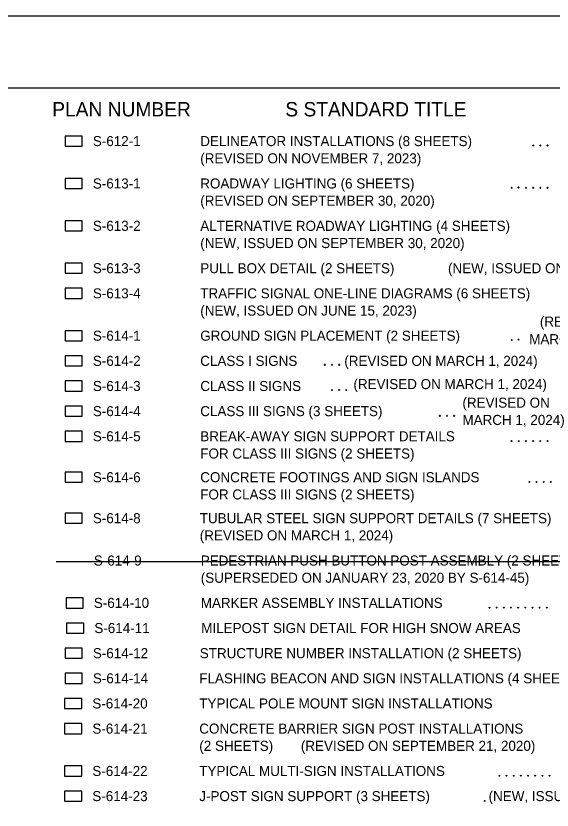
# Model space of a CAD drawing. Extents: x 0 to 1.42, y 0 to 0.92.
# Drawn here: x 0.9418 to 1.2532, y 0.4557 to 0.9167 of the extents above; entities that cross this region are included whole.
import ezdxf

# ---------------------------------------------------------------- set-up
doc = ezdxf.new("R2010")
doc.units = 0
for name, color, linetype in [('DRAFT_Text-Notes', 7, 'Continuous'), ('DRAFT_Text-Titles', 7, 'Continuous'), ('SHEET_Lines', 7, 'Continuous'), ('SHEET_Plot Boundary', 7, 'Continuous')]:
    doc.layers.add(name, color=color, linetype=linetype)

msp = doc.modelspace()

# ---------------------------------------------------------------- linework, layer by layer
at = {"layer": 'DRAFT_Text-Notes'}
for centre in [(1.2422, 0.84146), (1.24637, 0.84146), (1.25053, 0.84146), (1.2297, 0.81687), (1.23366, 0.81707), (1.23803, 0.81687), (1.2422, 0.81687), (1.24637, 0.81687), (1.25053, 0.81687), (1.2297, 0.7285), (1.23366, 0.72871), (1.12116, 0.71411), (1.12533, 0.71411), (1.12949, 0.71411), (1.12533, 0.69952), (1.12949, 0.69952), (1.13366, 0.69952), (1.18795, 0.68451), (1.19212, 0.68451), (1.19629, 0.68451), (1.22962, 0.66992), (1.23379, 0.66992), (1.23795, 0.66992), (1.24212, 0.66992), (1.24629, 0.66992), (1.25045, 0.66992), (1.23995, 0.64616), (1.24412, 0.64616), (1.24829, 0.64616), (1.25245, 0.64616), (1.21677, 0.57321), (1.22094, 0.57321), (1.2251, 0.57321), (1.22927, 0.57321), (1.23344, 0.57321), (1.2376, 0.57321), (1.24177, 0.57321), (1.24594, 0.57321), (1.2501, 0.57321), (1.22253, 0.47566), (1.2267, 0.47566), (1.23086, 0.47566), (1.23503, 0.47566), (1.2392, 0.47566), (1.24336, 0.47566), (1.24753, 0.47566), (1.2517, 0.47566), (1.21405, 0.461)]:
    msp.add_circle(centre, 0.000208, dxfattribs=at)
for centre, start, end in [((1.2422, 0.84146), 0, 180), ((1.2422, 0.84146), 180, 0), ((1.24637, 0.84146), 0, 180), ((1.24637, 0.84146), 180, 0), ((1.25053, 0.84146), 0, 180), ((1.25053, 0.84146), 180, 0), ((1.2297, 0.81687), 0, 180), ((1.2297, 0.81687), 180, 0), ((1.23366, 0.81707), 0, 180), ((1.23366, 0.81707), 180, 0), ((1.23803, 0.81687), 0, 180), ((1.23803, 0.81687), 180, 0), ((1.2422, 0.81687), 0, 180), ((1.2422, 0.81687), 180, 0), ((1.24637, 0.81687), 0, 180), ((1.24637, 0.81687), 180, 0), ((1.25053, 0.81687), 0, 180), ((1.25053, 0.81687), 180, 0), ((1.2297, 0.7285), 0, 180), ((1.2297, 0.7285), 180, 0), ((1.23366, 0.72871), 0, 180), ((1.23366, 0.72871), 180, 0), ((1.12116, 0.71411), 0, 180), ((1.12116, 0.71411), 180, 0), ((1.12533, 0.71411), 0, 180), ((1.12533, 0.71411), 180, 0), ((1.12949, 0.71411), 0, 180), ((1.12949, 0.71411), 180, 0), ((1.12533, 0.69952), 0, 180), ((1.12533, 0.69952), 180, 0), ((1.12949, 0.69952), 0, 180), ((1.12949, 0.69952), 180, 0), ((1.13366, 0.69952), 0, 180), ((1.13366, 0.69952), 180, 0), ((1.18795, 0.68451), 0, 180), ((1.18795, 0.68451), 180, 0), ((1.19212, 0.68451), 0, 180), ((1.19212, 0.68451), 180, 0), ((1.19629, 0.68451), 0, 180), ((1.19629, 0.68451), 180, 0), ((1.22962, 0.66992), 0, 180), ((1.22962, 0.66992), 180, 0), ((1.23379, 0.66992), 0, 180), ((1.23379, 0.66992), 180, 0), ((1.23795, 0.66992), 0, 180), ((1.23795, 0.66992), 180, 0), ((1.24212, 0.66992), 0, 180), ((1.24212, 0.66992), 180, 0), ((1.24629, 0.66992), 0, 180), ((1.24629, 0.66992), 180, 0), ((1.25045, 0.66992), 0, 180), ((1.25045, 0.66992), 180, 0), ((1.23995, 0.64616), 0, 180), ((1.23995, 0.64616), 180, 0), ((1.24412, 0.64616), 0, 180), ((1.24412, 0.64616), 180, 0), ((1.24829, 0.64616), 0, 180), ((1.24829, 0.64616), 180, 0), ((1.25245, 0.64616), 0, 180), ((1.25245, 0.64616), 180, 0), ((1.21677, 0.57321), 0, 180), ((1.21677, 0.57321), 180, 0), ((1.22094, 0.57321), 0, 180), ((1.22094, 0.57321), 180, 0), ((1.2251, 0.57321), 0, 180), ((1.2251, 0.57321), 180, 0), ((1.22927, 0.57321), 0, 180), ((1.22927, 0.57321), 180, 0), ((1.23344, 0.57321), 0, 180), ((1.23344, 0.57321), 180, 0), ((1.2376, 0.57321), 0, 180), ((1.2376, 0.57321), 180, 0), ((1.24177, 0.57321), 0, 180), ((1.24177, 0.57321), 180, 0), ((1.24594, 0.57321), 0, 180), ((1.24594, 0.57321), 180, 0), ((1.2501, 0.57321), 0, 180), ((1.2501, 0.57321), 180, 0), ((1.22253, 0.47566), 0, 180), ((1.22253, 0.47566), 180, 0), ((1.2267, 0.47566), 0, 180), ((1.2267, 0.47566), 180, 0), ((1.23086, 0.47566), 0, 180), ((1.23086, 0.47566), 180, 0), ((1.23503, 0.47566), 0, 180), ((1.23503, 0.47566), 180, 0), ((1.2392, 0.47566), 0, 180), ((1.2392, 0.47566), 180, 0), ((1.24336, 0.47566), 0, 180), ((1.24336, 0.47566), 180, 0), ((1.24753, 0.47566), 0, 180), ((1.24753, 0.47566), 180, 0), ((1.2517, 0.47566), 0, 180), ((1.2517, 0.47566), 180, 0), ((1.21405, 0.461), 0, 180), ((1.21405, 0.461), 180, 0)]:
    msp.add_arc(centre, 0.000208, start, end, dxfattribs=at)
at = {"layer": 'DRAFT_Text-Titles'}
msp.add_line((0.96512, 0.60007), (1.36191, 0.60007), dxfattribs=at)
at = {"layer": 'SHEET_Lines'}
msp.add_lwpolyline([(0.08333, 0.875), (1.375, 0.875), (1.375, 0.125), (0.08333, 0.125)], close=True, dxfattribs=at)
for points in [[(0.97038, 0.84102), (0.98035, 0.84102), (0.98035, 0.84691), (0.97038, 0.84691), (0.97038, 0.84102)], [(0.97038, 0.81643), (0.98035, 0.81643), (0.98035, 0.82232), (0.97038, 0.82232), (0.97038, 0.81643)], [(0.97038, 0.79184), (0.98035, 0.79184), (0.98035, 0.79773), (0.97038, 0.79773), (0.97038, 0.79184)], [(0.97038, 0.76725), (0.98035, 0.76725), (0.98035, 0.77313), (0.97038, 0.77313), (0.97038, 0.76725)], [(0.97038, 0.75266), (0.98035, 0.75266), (0.98035, 0.75854), (0.97038, 0.75854), (0.97038, 0.75266)], [(0.97038, 0.72806), (0.98035, 0.72806), (0.98035, 0.73395), (0.97038, 0.73395), (0.97038, 0.72806)], [(0.97038, 0.71347), (0.98035, 0.71347), (0.98035, 0.71936), (0.97038, 0.71936), (0.97038, 0.71347)], [(0.97038, 0.69888), (0.98035, 0.69888), (0.98035, 0.70477), (0.97038, 0.70477), (0.97038, 0.69888)], [(0.97038, 0.68429), (0.98035, 0.68429), (0.98035, 0.69017), (0.97038, 0.69017), (0.97038, 0.68429)], [(0.97038, 0.66969), (0.98035, 0.66969), (0.98035, 0.67558), (0.97038, 0.67558), (0.97038, 0.66969)], [(0.97038, 0.64593), (0.98035, 0.64593), (0.98035, 0.65182), (0.97038, 0.65182), (0.97038, 0.64593)], [(0.97038, 0.62217), (0.98035, 0.62217), (0.98035, 0.62805), (0.97038, 0.62805), (0.97038, 0.62217)], [(0.97096, 0.57298), (0.98093, 0.57298), (0.98093, 0.57887), (0.97096, 0.57887), (0.97096, 0.57298)], [(0.97125, 0.55839), (0.98122, 0.55839), (0.98122, 0.56428), (0.97125, 0.56428), (0.97125, 0.55839)], [(0.97038, 0.5438), (0.98035, 0.5438), (0.98035, 0.54968), (0.97038, 0.54968), (0.97038, 0.5438)], [(0.97038, 0.52921), (0.98035, 0.52921), (0.98035, 0.53509), (0.97038, 0.53509), (0.97038, 0.52921)], [(0.97009, 0.51461), (0.98006, 0.51461), (0.98006, 0.5205), (0.97009, 0.5205), (0.97009, 0.51461)], [(0.97009, 0.50002), (0.98006, 0.50002), (0.98006, 0.50591), (0.97009, 0.50591), (0.97009, 0.50002)], [(0.97009, 0.47543), (0.98006, 0.47543), (0.98006, 0.48132), (0.97009, 0.48132), (0.97009, 0.47543)], [(0.97009, 0.46084), (0.98006, 0.46084), (0.98006, 0.46672), (0.97009, 0.46672), (0.97009, 0.46084)]]:
    msp.add_lwpolyline(points, dxfattribs=at)
at = {"layer": 'SHEET_Plot Boundary'}
msp.add_lwpolyline([(0, 0.91667), (1.41667, 0.91667), (1.41667, 0), (0, 0)], close=True, dxfattribs=at)

# ---------------------------------------------------------------- texts
at = {"layer": 'DRAFT_Text-Notes'}
for s, height, p in [('S-612-1', 0.005833, (0.98651, 0.84108)), ('DELINEATOR INSTALLATIONS (8 SHEETS)', 0.0058333, (1.04888, 0.84108)), ('S-613-1', 0.005833, (0.98651, 0.81648)), ('ROADWAY LIGHTING (6 SHEETS)', 0.0058333, (1.04888, 0.81648)), ('S-613-2', 0.005833, (0.98651, 0.79189)), ('ALTERNATIVE ROADWAY LIGHTING (4 SHEETS)', 0.0058333, (1.04888, 0.79189)), ('S-613-3', 0.005833, (0.98651, 0.7673)), ('PULL BOX DETAIL (2 SHEETS)', 0.0058333, (1.04888, 0.7673)), ('S-613-4', 0.005833, (0.98651, 0.75271)), ('TRAFFIC SIGNAL ONE-LINE DIAGRAMS (6 SHEETS)', 0.0058333, (1.04888, 0.75271)), ('S-614-1', 0.005833, (0.98651, 0.72812)), ('GROUND SIGN PLACEMENT (2 SHEETS)', 0.0058333, (1.04888, 0.72812)), ('S-614-2', 0.005833, (0.98651, 0.71352)), ('CLASS I SIGNS', 0.0058333, (1.04888, 0.71352)), ('S-614-3', 0.005833, (0.98651, 0.69893)), ('CLASS II SIGNS', 0.0058333, (1.04888, 0.69893)), ('S-614-4', 0.005833, (0.98651, 0.68434)), ('CLASS III SIGNS (3 SHEETS)', 0.0058333, (1.04888, 0.68434)), ('S-614-5', 0.005833, (0.98651, 0.66975)), ('BREAK-AWAY SIGN SUPPORT DETAILS', 0.0058333, (1.04888, 0.66975)), ('FOR CLASS III SIGNS (2 SHEETS)', 0.0058333, (1.04888, 0.65975)), ('S-614-6', 0.005833, (0.98651, 0.64598)), ('CONCRETE FOOTINGS AND SIGN ISLANDS', 0.0058333, (1.04888, 0.64598)), ('FOR CLASS III SIGNS (2 SHEETS)', 0.0058333, (1.04888, 0.63598)), ('S-614-8', 0.005833, (0.98651, 0.62222)), ('TUBULAR STEEL SIGN SUPPORT DETAILS (7 SHEETS)', 0.0058333, (1.0486, 0.62222)), ('S-614-9', 0.005833, (0.98709, 0.59763)), ('PEDESTRIAN PUSH BUTTON POST ASSEMBLY (2 SHEETS)', 0.0058333, (1.04917, 0.59763)), ('S-614-10', 0.005833, (0.98709, 0.57304)), ('MARKER ASSEMBLY INSTALLATIONS', 0.0058333, (1.04917, 0.57304)), ('S-614-11', 0.005833, (0.98738, 0.55844)), ('MILEPOST SIGN DETAIL FOR HIGH SNOW AREAS', 0.0058333, (1.04946, 0.55844)), ('S-614-12', 0.005833, (0.98651, 0.54385)), ('STRUCTURE NUMBER INSTALLATION (2 SHEETS)', 0.0058333, (1.04859, 0.54385)), ('S-614-14', 0.005833, (0.98651, 0.52926)), ('FLASHING BEACON AND SIGN INSTALLATIONS (4 SHEETS)', 0.0058333, (1.0483, 0.52926)), ('S-614-20', 0.005833, (0.98622, 0.51467)), ('TYPICAL POLE MOUNT SIGN INSTALLATIONS', 0.0058333, (1.0483, 0.51467)), ('S-614-21', 0.005833, (0.98622, 0.50007)), ('CONCRETE BARRIER SIGN POST INSTALLATIONS', 0.0058333, (1.0483, 0.50007)), ('(2 SHEETS)', 0.005833, (1.0483, 0.49007)), ('S-614-22', 0.005833, (0.98622, 0.47548)), ('TYPICAL MULTI-SIGN INSTALLATIONS', 0.0058333, (1.0483, 0.47548)), ('S-614-23', 0.005833, (0.98622, 0.46089)), ('J-POST SIGN SUPPORT (3 SHEETS)', 0.0058333, (1.0483, 0.46089))]:
    msp.add_text(s, height=height, dxfattribs=at).set_placement(p)
at = {"layer": 'DRAFT_Text-Titles'}
for s, height, p in [('S STANDARD TITLE', 0.0083333, (1.09825, 0.85831)), ('PLAN NUMBER', 0.0083333, (0.96292, 0.85831)), ('(REVISED ON NOVEMBER 7, 2023)', 0.0058333, (1.04888, 0.83108)), ('(REVISED ON SEPTEMBER 30, 2020)', 0.0058333, (1.04888, 0.80648)), ('(NEW, ISSUED ON SEPTEMBER 30, 2020)', 0.0058333, (1.04888, 0.78189)), ('(NEW, ISSUED ON APRIL 4, 2024)', 0.0058333, (1.19271, 0.7673)), ('(NEW, ISSUED ON JUNE 15, 2023)', 0.0058333, (1.04888, 0.74271)), ('(REVISED ON', 0.0058333, (1.24606, 0.73631)), ('MARCH 1, 2024)', 0.0058333, (1.23988, 0.7261)), ('(REVISED ON MARCH 1, 2024)', 0.0058333, (1.1325, 0.71352)), ('(REVISED ON MARCH 1, 2024)', 0.0058333, (1.13782, 0.70004)), ('(REVISED ON', 0.0058333, (1.2011, 0.68925)), ('MARCH 1, 2024)', 0.0058333, (1.2011, 0.67925)), ('(REVISED ON MARCH 1, 2024)', 0.0058333, (1.0486, 0.61222)), ('(SUPERSEDED ON JANUARY 23, 2020 BY S-614-45)', 0.0058333, (1.04917, 0.58763)), ('(REVISED ON SEPTEMBER 21, 2020)', 0.0058333, (1.10729, 0.49007)), ('(NEW, ISSUED ON MARCH 1, 2024)', 0.0058333, (1.21628, 0.46089))]:
    msp.add_text(s, height=height, dxfattribs=at).set_placement(p)

doc.saveas('drawing.dxf')
